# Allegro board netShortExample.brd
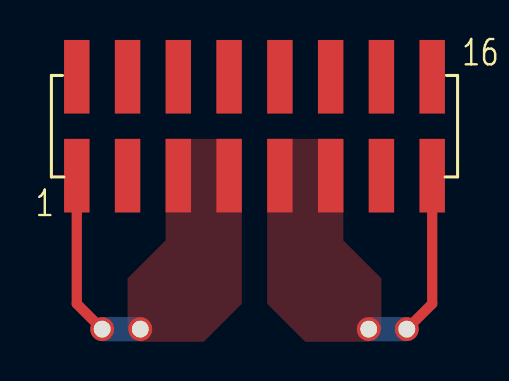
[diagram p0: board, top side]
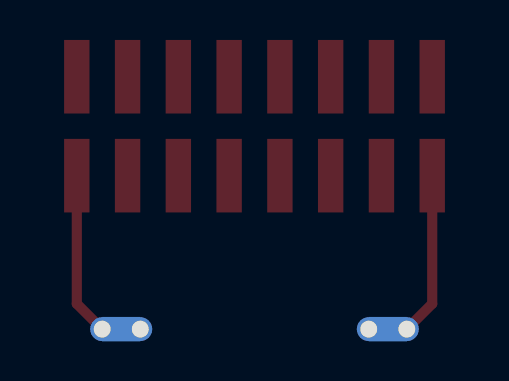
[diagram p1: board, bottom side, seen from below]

No outline. copper layers: TOP, BOTTOM. Coordinates in mm from the lowest, leftmost part position.

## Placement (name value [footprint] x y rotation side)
NS1  -  [NET_SHORT_TH]  0 0 180 bottom
NS2  -  [NET_SHORT_TH]  11.43 0 0 bottom
P1  -  [C16_2X8_P1_HDR]  5.71 10.16 0 top

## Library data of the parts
NS1 NS2 = NET_SHORT: alternate symbols: (NET_SHORT_SM,NET_SHORT_VIA,NET_SHORT_0402)
P1 = HDR_2X8: part number: HDR_2X8_CONN-TSM_108_DV,VERTICAL,SAMTEC,TSM-108-01-L-DV-P,C16_2X8_P1_HDR,000030

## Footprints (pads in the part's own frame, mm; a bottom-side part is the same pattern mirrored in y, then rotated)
C16_2X8_P1_HDR
  rect 1.27x3.683 smd: 1(-8.89,-2.477) 2(-8.89,2.477) 3(-6.35,-2.477) 4(-6.35,2.477) 5(-3.81,-2.477) 6(-3.81,2.477) 7(-1.27,-2.477) 8(-1.27,2.477) 9(1.27,-2.477) 10(1.27,2.477) 11(3.81,-2.477) 12(3.81,2.477) 13(6.35,-2.477) 14(6.35,2.477) 15(8.89,-2.477) 16(8.89,2.477)
NET_SHORT_TH
  round 1.194 hole 0.838: 1(0,0) 2(1.905,0)

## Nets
5V_SENSE: NS1.2(B) P1.1(P1)
GND: NS2.1(A) P1.9(P9) P1.11(P11)
GND_SENSE: NS2.2(B) P1.15(P15)
P5V: NS1.1(A) P1.5(P5) P1.7(P7)

Pads without a net: P1 2 3 4 6 8 10 12 13 14 16

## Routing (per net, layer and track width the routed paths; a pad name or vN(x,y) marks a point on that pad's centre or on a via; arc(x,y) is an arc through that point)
5V_SENSE: length 8.2
  TOP w0.508: P1.1 -3.18,1.27 NS1.2
GND_SENSE: length 8.2
  TOP w0.508: P1.15 14.6,1.27 NS2.2

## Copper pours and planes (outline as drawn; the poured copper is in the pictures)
GND on BOTTOM (solid shape): 13.33,-0.61 11.43,-0.61 11.43,0.61 13.33,0.61
GND on TOP: 6.35,9.53 6.35,1.27 8.25,-0.64 11.43,-0.64 12.06,0 12.06,2.54 10.16,4.44 10.16,9.53
P5V on BOTTOM (solid shape): 0,-0.61 -1.91,-0.61 -1.91,0.61 0,0.61
P5V on TOP: 5.08,9.53 5.08,1.27 3.18,-0.64 0,-0.64 -0.63,0 -0.63,2.54 1.27,4.44 1.27,9.53

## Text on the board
User.Comments: 1. THE FOLLOWING ARE INTENTIONAL SHORTS DUE TO DESIGN PURPOSES: | 1. GND and GND_SENSE | 2. P5V and 5V_SENSE
